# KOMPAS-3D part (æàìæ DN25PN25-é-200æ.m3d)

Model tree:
1. Объединить компоненты:1  (labels: СЕНС DN25PN25-В-200С)

Referenced files in D:\Савин\!СЕНСОР\3D для заказчика\!Новый перечень\СЕНС\4. СЕНС-В-200С\DN25\: СЕНС DN25PN25-В-200С.a3d
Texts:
  СЕНС DN25PN25-В-200С
  ООО НПП Сенсор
